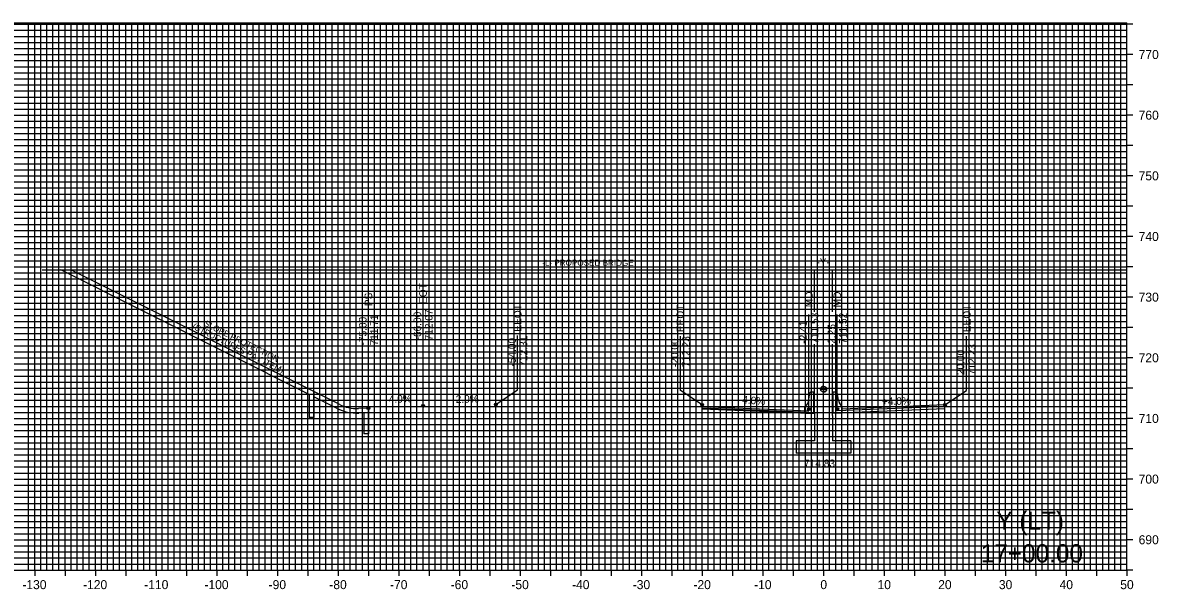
# Model space of a CAD drawing. Extents: x -255 to 55, y 682 to 775.
# Drawn here: x -132 to 55.2, y 681.8 to 775.3 of the extents above; entities that cross this region are included whole.
import ezdxf

# ---------------------------------------------------------------- set-up
doc = ezdxf.new("R2010")
doc.units = 0
for name, color, linetype in [('Default', 7, 'Continuous'), ('Draft_Corridor_Graphics_Conceptual', 7, 'Continuous'), ('Draft_Corridor_Point_Control', 7, 'Continuous'), ('E_NCDOT_Vertical_Profile_Ground_Line', 7, 'Continuous'), ('P_HYD_Contour_Major', 7, 'Continuous'), ('P_HYD_Contour_Minor', 7, 'Continuous'), ('P_HYD_TC_Ditch_DDE', 7, 'Continuous'), ('P_HYD_TC_Ditch_UCE', 7, 'Continuous'), ('P_HYD_TC_Surface_Grass', 7, 'Continuous'), ('P_HYD_TL_Slope_Stake_Fill', 7, 'Continuous'), ('P_HYD_Watershed_Grass_C_03', 7, 'Continuous'), ('P_HYD_Watershed_Impervious_C_09', 7, 'Continuous'), ('P_NCDOT_Terrain_Breakline', 7, 'Continuous'), ('P_NCDOT_Terrain_Flow_Arrows', 7, 'Continuous'), ('P_NCDOT_Terrain_Hole', 7, 'Continuous'), ('P_NCDOT_Terrain_Island', 7, 'Continuous'), ('P_NCDOT_Terrain_Points_High', 7, 'Continuous'), ('Scratch_Level_0', 7, 'Continuous')]:
    doc.layers.add(name, color=color, linetype=linetype)

msp = doc.modelspace()

# ---------------------------------------------------------------- linework, layer by layer
at = {"layer": 'Default'}
for p, q in [((-128.74, 734.49), (49.99, 734.49)), ((0, 714.83), (0, 734.41)), ((-20.03, 711.57), (-2.44, 710.86)), ((-20.02, 711.73), (-2.43, 711.03)), ((-20.01, 711.98), (-2.42, 711.28)), ((20, 711.99), (2.28, 711.28)), ((20, 711.57), (2.3, 710.86))]:
    msp.add_line(p, q, dxfattribs=at)
at = {"layer": 'Draft_Corridor_Point_Control'}
for p, q in [((0, 715.33), (0, 714.33)), ((-0.5, 714.83), (0.5, 714.83))]:
    msp.add_line(p, q, dxfattribs=at)
for points in [[(-0.5, 714.83), (0, 714.83), (0, 715.33)], [(0.5, 714.83), (0, 714.83), (0, 714.33)]]:
    msp.add_lwpolyline(points, dxfattribs=at)
msp.add_circle((0, 714.83), 0.5, dxfattribs=at)
for start, end in [(90, 180), (270, 0)]:
    msp.add_arc((0, 714.83), 0.5, start, end, dxfattribs=at)
at = {"layer": 'P_HYD_Contour_Major'}
for p, q in [((-131, 685), (-131, 775.25)), ((-129, 685), (-129, 775.25)), ((-128, 685), (-128, 775.25)), ((-127, 685), (-127, 775.25)), ((-126, 685), (-126, 775.25)), ((-124, 685), (-124, 775.25)), ((-123, 685), (-123, 775.25)), ((-122, 685), (-122, 775.25)), ((-121, 685), (-121, 775.25)), ((-119, 685), (-119, 775.25)), ((-118, 685), (-118, 775.25)), ((-117, 685), (-117, 775.25)), ((-116, 685), (-116, 775.25)), ((-114, 685), (-114, 775.25)), ((-113, 685), (-113, 775.25)), ((-112, 685), (-112, 775.25)), ((-111, 685), (-111, 775.25)), ((-109, 685), (-109, 775.25)), ((-108, 685), (-108, 775.25)), ((-107, 685), (-107, 775.25)), ((-106, 685), (-106, 775.25)), ((-104, 685), (-104, 775.25)), ((-103, 685), (-103, 775.25)), ((-102, 685), (-102, 775.25)), ((-101, 685), (-101, 775.25)), ((-99, 685), (-99, 775.25)), ((-98, 685), (-98, 775.25)), ((-97, 685), (-97, 775.25)), ((-96, 685), (-96, 775.25)), ((-94, 685), (-94, 775.25)), ((-93, 685), (-93, 775.25)), ((-92, 685), (-92, 775.25)), ((-91, 685), (-91, 775.25)), ((-89, 685), (-89, 775.25)), ((-88, 685), (-88, 775.25)), ((-87, 685), (-87, 775.25)), ((-86, 685), (-86, 775.25)), ((-84, 685), (-84, 775.25)), ((-83, 685), (-83, 775.25)), ((-82, 685), (-82, 775.25)), ((-81, 685), (-81, 775.25)), ((-79, 685), (-79, 775.25)), ((-78, 685), (-78, 775.25)), ((-77, 685), (-77, 775.25)), ((-76, 685), (-76, 775.25)), ((-74, 685), (-74, 775.25)), ((-73, 685), (-73, 775.25)), ((-72, 685), (-72, 775.25)), ((-71, 685), (-71, 775.25)), ((-69, 685), (-69, 775.25)), ((-68, 685), (-68, 775.25)), ((-67, 685), (-67, 775.25)), ((-66, 685), (-66, 775.25)), ((-64, 685), (-64, 775.25)), ((-63, 685), (-63, 775.25)), ((-62, 685), (-62, 775.25)), ((-61, 685), (-61, 775.25)), ((-59, 685), (-59, 775.25)), ((-58, 685), (-58, 775.25)), ((-57, 685), (-57, 775.25)), ((-56, 685), (-56, 775.25)), ((-54, 685), (-54, 775.25)), ((-53, 685), (-53, 775.25)), ((-52, 685), (-52, 775.25)), ((-51, 685), (-51, 775.25)), ((-49, 685), (-49, 775.25)), ((-48, 685), (-48, 775.25)), ((-47, 685), (-47, 775.25)), ((-46, 685), (-46, 775.25)), ((-44, 685), (-44, 775.25)), ((-43, 685), (-43, 775.25)), ((-42, 685), (-42, 775.25)), ((-41, 685), (-41, 775.25)), ((-39, 685), (-39, 775.25)), ((-38, 685), (-38, 775.25)), ((-37, 685), (-37, 775.25)), ((-36, 685), (-36, 775.25)), ((-34, 685), (-34, 775.25)), ((-33, 685), (-33, 775.25)), ((-32, 685), (-32, 775.25)), ((-31, 685), (-31, 775.25)), ((-29, 685), (-29, 775.25)), ((-28, 685), (-28, 775.25)), ((-27, 685), (-27, 775.25)), ((-26, 685), (-26, 775.25)), ((-24, 685), (-24, 775.25)), ((-23, 685), (-23, 775.25)), ((-22, 685), (-22, 775.25)), ((-21, 685), (-21, 775.25)), ((-19, 685), (-19, 775.25)), ((-18, 685), (-18, 775.25)), ((-17, 685), (-17, 775.25)), ((-16, 685), (-16, 775.25)), ((-14, 685), (-14, 775.25)), ((-13, 685), (-13, 775.25)), ((-12, 685), (-12, 775.25)), ((-11, 685), (-11, 775.25)), ((-9, 685), (-9, 775.25)), ((-8, 685), (-8, 775.25)), ((-7, 685), (-7, 775.25)), ((-6, 685), (-6, 775.25)), ((-4, 685), (-4, 775.25)), ((-3, 685), (-3, 775.25)), ((-2, 685), (-2, 775.25)), ((-1, 685), (-1, 775.25)), ((1, 685), (1, 775.25)), ((2, 685), (2, 775.25)), ((3, 685), (3, 775.25)), ((4, 685), (4, 775.25)), ((6, 685), (6, 775.25)), ((7, 685), (7, 775.25)), ((8, 685), (8, 775.25)), ((9, 685), (9, 775.25)), ((11, 685), (11, 775.25)), ((12, 685), (12, 775.25)), ((13, 685), (13, 775.25)), ((14, 685), (14, 775.25)), ((16, 685), (16, 775.25)), ((17, 685), (17, 775.25)), ((18, 685), (18, 775.25)), ((19, 685), (19, 775.25)), ((21, 685), (21, 775.25)), ((22, 685), (22, 775.25)), ((23, 685), (23, 775.25)), ((24, 685), (24, 775.25)), ((26, 685), (26, 775.25)), ((27, 685), (27, 775.25)), ((28, 685), (28, 775.25)), ((29, 685), (29, 775.25)), ((31, 685), (31, 775.25)), ((32, 685), (32, 775.25)), ((33, 685), (33, 775.25)), ((34, 685), (34, 775.25)), ((36, 685), (36, 775.25)), ((37, 685), (37, 775.25)), ((38, 685), (38, 775.25)), ((39, 685), (39, 775.25)), ((41, 685), (41, 775.25)), ((42, 685), (42, 775.25)), ((43, 685), (43, 775.25)), ((44, 685), (44, 775.25)), ((46, 685), (46, 775.25)), ((47, 685), (47, 775.25)), ((48, 685), (48, 775.25)), ((49, 685), (49, 775.25)), ((-250, 774), (50, 774)), ((-250, 773), (50, 773)), ((-250, 772), (50, 772)), ((-250, 771), (50, 771)), ((-250, 769), (50, 769)), ((-250, 768), (50, 768)), ((-250, 767), (50, 767)), ((-250, 766), (50, 766)), ((-250, 764), (50, 764)), ((-250, 763), (50, 763)), ((-250, 762), (50, 762)), ((-250, 761), (50, 761)), ((-250, 759), (50, 759)), ((-250, 758), (50, 758)), ((-250, 757), (50, 757)), ((-250, 756), (50, 756)), ((-250, 754), (50, 754)), ((-250, 753), (50, 753)), ((-250, 752), (50, 752)), ((-250, 751), (50, 751)), ((-250, 749), (50, 749)), ((-250, 748), (50, 748)), ((-250, 747), (50, 747)), ((-250, 746), (50, 746)), ((-250, 744), (50, 744)), ((-250, 743), (50, 743)), ((-250, 742), (50, 742)), ((-250, 741), (50, 741)), ((-250, 739), (50, 739)), ((-250, 738), (50, 738)), ((-250, 737), (50, 737)), ((-250, 736), (50, 736)), ((-250, 734), (50, 734)), ((-250, 733), (50, 733)), ((-250, 732), (50, 732)), ((-250, 731), (50, 731)), ((-250, 729), (50, 729)), ((-250, 728), (50, 728)), ((-250, 727), (50, 727)), ((-250, 726), (50, 726)), ((-250, 724), (50, 724)), ((-250, 723), (50, 723)), ((-250, 722), (50, 722)), ((-250, 721), (50, 721)), ((-250, 719), (50, 719)), ((-250, 718), (50, 718)), ((-250, 717), (50, 717)), ((-250, 716), (50, 716)), ((-250, 714), (50, 714)), ((-250, 713), (50, 713)), ((-250, 712), (50, 712)), ((-250, 711), (50, 711)), ((-250, 709), (50, 709)), ((-250, 708), (50, 708)), ((-250, 707), (50, 707)), ((-250, 706), (50, 706)), ((-250, 704), (50, 704)), ((-250, 703), (50, 703)), ((-250, 702), (50, 702)), ((-250, 701), (50, 701)), ((-250, 699), (50, 699)), ((-250, 698), (50, 698)), ((-250, 697), (50, 697)), ((-250, 696), (50, 696)), ((-250, 694), (50, 694)), ((-250, 693), (50, 693)), ((-250, 692), (50, 692)), ((-250, 691), (50, 691)), ((-250, 689), (50, 689)), ((-250, 688), (50, 688)), ((-250, 687), (50, 687)), ((-250, 686), (50, 686))]:
    msp.add_line(p, q, dxfattribs=at)
at = {"layer": 'P_HYD_Contour_Minor'}
for p, q in [((-250, 775), (50, 775)), ((-130, 685), (-130, 775.25)), ((-125, 685), (-125, 775.25)), ((-120, 685), (-120, 775.25)), ((-115, 685), (-115, 775.25)), ((-110, 685), (-110, 775.25)), ((-105, 685), (-105, 775.25)), ((-100, 685), (-100, 775.25)), ((-95, 685), (-95, 775.25)), ((-90, 685), (-90, 775.25)), ((-85, 685), (-85, 775.25)), ((-80, 685), (-80, 775.25)), ((-75, 685), (-75, 775.25)), ((-70, 685), (-70, 775.25)), ((-65, 685), (-65, 775.25)), ((-60, 685), (-60, 775.25)), ((-55, 685), (-55, 775.25)), ((-50, 685), (-50, 775.25)), ((-45, 685), (-45, 775.25)), ((-40, 685), (-40, 775.25)), ((-35, 685), (-35, 775.25)), ((-30, 685), (-30, 775.25)), ((-25, 685), (-25, 775.25)), ((-20, 685), (-20, 775.25)), ((-15, 685), (-15, 775.25)), ((-10, 685), (-10, 775.25)), ((-5, 685), (-5, 775.25)), ((0, 685), (0, 775.25)), ((5, 685), (5, 775.25)), ((10, 685), (10, 775.25)), ((15, 685), (15, 775.25)), ((20, 685), (20, 775.25)), ((25, 685), (25, 775.25)), ((30, 685), (30, 775.25)), ((35, 685), (35, 775.25)), ((40, 685), (40, 775.25)), ((45, 685), (45, 775.25)), ((50.96, 775), (50, 775)), ((-250, 770), (50, 770)), ((50.96, 770), (50, 770)), ((-250, 765), (50, 765)), ((50.96, 765), (50, 765)), ((-250, 760), (50, 760)), ((50.96, 760), (50, 760)), ((-250, 755), (50, 755)), ((50.96, 755), (50, 755)), ((-250, 750), (50, 750)), ((50.96, 750), (50, 750)), ((-250, 745), (50, 745)), ((50.96, 745), (50, 745)), ((-250, 740), (50, 740)), ((50.96, 740), (50, 740)), ((-250, 735), (50, 735)), ((50.96, 735), (50, 735)), ((-250, 730), (50, 730)), ((50.96, 730), (50, 730)), ((-250, 725), (50, 725)), ((50.96, 725), (50, 725)), ((-250, 720), (50, 720)), ((50.96, 720), (50, 720)), ((-250, 715), (50, 715)), ((50.96, 715), (50, 715)), ((-250, 710), (50, 710)), ((50.96, 710), (50, 710)), ((-250, 705), (50, 705)), ((50.96, 705), (50, 705)), ((-250, 700), (50, 700)), ((50.96, 700), (50, 700)), ((-250, 695), (50, 695)), ((50.96, 695), (50, 695)), ((-250, 690), (50, 690)), ((50.96, 690), (50, 690)), ((-130, 685), (-130, 684.04)), ((-125, 685), (-125, 684.04)), ((-120, 685), (-120, 684.04)), ((-115, 685), (-115, 684.04)), ((-110, 685), (-110, 684.04)), ((-105, 685), (-105, 684.04)), ((-100, 685), (-100, 684.04)), ((-95, 685), (-95, 684.04)), ((-90, 685), (-90, 684.04)), ((-85, 685), (-85, 684.04)), ((-80, 685), (-80, 684.04)), ((-75, 685), (-75, 684.04)), ((-70, 685), (-70, 684.04)), ((-65, 685), (-65, 684.04)), ((-60, 685), (-60, 684.04)), ((-55, 685), (-55, 684.04)), ((-50, 685), (-50, 684.04)), ((-45, 685), (-45, 684.04)), ((-40, 685), (-40, 684.04)), ((-35, 685), (-35, 684.04)), ((-30, 685), (-30, 684.04)), ((-25, 685), (-25, 684.04)), ((-20, 685), (-20, 684.04)), ((-15, 685), (-15, 684.04)), ((-10, 685), (-10, 684.04)), ((-5, 685), (-5, 684.04)), ((0, 685), (0, 684.04)), ((5, 685), (5, 684.04)), ((10, 685), (10, 684.04)), ((15, 685), (15, 684.04)), ((20, 685), (20, 684.04)), ((25, 685), (25, 684.04)), ((30, 685), (30, 684.04)), ((35, 685), (35, 684.04)), ((40, 685), (40, 684.04)), ((45, 685), (45, 684.04)), ((50, 685), (50, 684.04)), ((50.96, 685), (50, 685))]:
    msp.add_line(p, q, dxfattribs=at)
at = {"layer": 'P_HYD_TC_Ditch_DDE'}
for p, q in [((-130, 685), (-130, 775.25)), ((-120, 685), (-120, 775.25)), ((-110, 685), (-110, 775.25)), ((-100, 685), (-100, 775.25)), ((-90, 685), (-90, 775.25)), ((-80, 685), (-80, 775.25)), ((-70, 685), (-70, 775.25)), ((-60, 685), (-60, 775.25)), ((-50, 685), (-50, 775.25)), ((-50, 685), (-50, 775.25)), ((-40, 685), (-40, 775.25)), ((-30, 685), (-30, 775.25)), ((-20, 685), (-20, 775.25)), ((-10, 685), (-10, 775.25)), ((0, 685), (0, 775.25)), ((10, 685), (10, 775.25)), ((20, 685), (20, 775.25)), ((30, 685), (30, 775.25)), ((40, 685), (40, 775.25)), ((-250, 770), (50, 770)), ((-250, 760), (50, 760)), ((-250, 750), (50, 750)), ((-250, 740), (50, 740)), ((-250, 730), (50, 730)), ((-250, 720), (50, 720)), ((-250, 710), (50, 710)), ((-250, 700), (50, 700)), ((-250, 690), (50, 690))]:
    msp.add_line(p, q, dxfattribs=at)
at = {"layer": 'P_HYD_TC_Ditch_UCE'}
for centre in [(0, 714.83), (0, 714.82), (-75, 711.71), (-75, 711.71), (-66, 712.07), (-66, 712.07), (-54, 712.31), (-54, 712.31), (-20, 712.23), (-2.41, 711.53), (2.25, 711.52), (20, 712.23)]:
    msp.add_circle(centre, 0.05, dxfattribs=at)
at = {"layer": 'P_HYD_TL_Slope_Stake_Fill'}
for p, q in [((-250, 775.25), (50, 775.25)), ((50, 685), (50, 775.25)), ((-250, 685), (50, 685))]:
    msp.add_line(p, q, dxfattribs=at)
at = {"layer": 'P_HYD_Watershed_Impervious_C_09'}
for p, q in [((-50.44, 714.71), (-50.44, 723.66)), ((-23.56, 714.63), (-23.56, 723.58)), ((23.56, 714.63), (23.56, 723.58)), ((-54, 712.31), (-50.44, 714.71)), ((-20, 712.23), (-23.56, 714.63)), ((20, 712.23), (23.56, 714.63))]:
    msp.add_line(p, q, dxfattribs=at)
at = {"layer": 'P_NCDOT_Terrain_Hole'}
msp.add_line((20, 712.23), (3.08, 711.56), dxfattribs=at)
at = {"layer": 'P_NCDOT_Terrain_Island'}
for points in [[(-2.46, 712.83), (-2.25, 714.24)], [(-1.58, 710.81), (-1.58, 714.31), (-2.17, 714.31)], [(1.58, 710.91), (1.58, 714.41), (2.17, 714.41)], [(2.46, 712.94), (2.25, 714.34)], [(-1.58, 710.81), (-3.08, 710.81), (-3.08, 711.56), (-3.08, 711.81), (-2.6, 712.48)], [(1.58, 710.91), (3.08, 710.91), (3.08, 711.66), (3.08, 711.91), (2.6, 712.58)]]:
    msp.add_lwpolyline(points, dxfattribs=at)
for centre, radius, start, end in [((-2.17, 714.22), 0.0833, 90, 171.4692), ((2.17, 714.33), 0.0833, 8.5308, 90), ((-3.29, 712.96), 0.833, 325.008, 351.4692), ((3.29, 713.06), 0.833, 188.5308, 214.992)]:
    msp.add_arc(centre, radius, start, end, dxfattribs=at)
at = {"layer": 'P_NCDOT_Terrain_Points_High'}
for p, q in [((-84.75, 713.96), (-125.71, 734.49)), ((-79.83, 712.34), (-124.04, 734.49)), ((-1.5, 727.6), (-1.5, 734.38)), ((1.5, 727.6), (1.5, 734.38)), ((-1.5, 710.98), (-1.5, 722.26)), ((1.5, 710.5), (1.5, 722.26)), ((-84.75, 713.96), (-84.75, 710.18)), ((-84, 714.43), (-84, 710.18)), ((-80.17, 711.67), (-84, 713.59)), ((-75, 711.71), (-76.63, 711.65)), ((-75, 711.71), (-75, 707.45)), ((-84, 710.18), (-84.75, 710.18)), ((-75.75, 710.93), (-76.6, 710.9)), ((-75.75, 710.93), (-75.75, 707.45)), ((-1.5, 710.98), (-1.5, 706.29)), ((1.5, 710.5), (1.5, 706.29)), ((-75, 707.45), (-75.75, 707.45)), ((-1.5, 706.29), (-4.5, 706.29)), ((-4.5, 706.29), (-4.5, 704.29)), ((4.5, 706.29), (1.5, 706.29)), ((4.5, 706.29), (4.5, 704.29)), ((4.5, 704.29), (-4.5, 704.29))]:
    msp.add_line(p, q, dxfattribs=at)
for radius in [7.32, 6.57]:
    msp.add_arc((-76.89, 718.21), radius, 243.3788, 272.2621, dxfattribs=at)
at = {"layer": 'Scratch_Level_0'}
for p, q in [((-75, 711.71), (-75, 727.31)), ((-66, 712.07), (-66, 727.67)), ((-2.41, 711.53), (-2.41, 727.13)), ((2.25, 711.52), (2.25, 727.12))]:
    msp.add_line(p, q, dxfattribs=at)
for centre in [(-75, 711.71), (-66, 712.07), (-54, 712.31), (-20, 712.23), (-2.41, 711.53), (2.25, 711.52), (20, 712.23)]:
    msp.add_circle(centre, 0.24, dxfattribs=at)

# ---------------------------------------------------------------- texts
at = {"layer": 'Draft_Corridor_Graphics_Conceptual'}
for s, rotation, p in [('-4.0%', 1.512, (-72.2, 712.55)), ('-2.0%', 1.1835, (-61.17, 712.54)), ('-4.0%', 355.2171, (-14, 712.55)), ('+4.0%', 1.512, (9.63, 712.17))]:
    msp.add_text(s, height=1.248, rotation=rotation, dxfattribs=at).set_placement(p)
at = {"layer": 'E_NCDOT_Vertical_Profile_Ground_Line'}
for s, height, p in [('770', 1.488, (51.92, 769.26)), ('760', 1.488, (51.92, 759.26)), ('750', 1.488, (51.92, 749.26)), ('740', 1.488, (51.92, 739.26)), ('730', 1.488, (51.92, 729.26)), ('720', 1.488, (51.92, 719.26)), ('710', 1.488, (51.92, 709.26)), ('700', 1.488, (51.92, 699.26)), ('690', 1.488, (51.92, 689.26)), ('-130', 1.488, (-132.03, 681.86)), ('-120', 1.488, (-122.03, 681.86)), ('-110', 1.488, (-111.95, 681.86)), ('-100', 1.488, (-102.03, 681.86)), ('-90', 1.488, (-91.45, 681.86)), ('-80', 1.488, (-81.45, 681.86)), ('-70', 1.488, (-71.45, 681.86)), ('-60', 1.488, (-61.45, 681.86)), ('-50', 1.488, (-51.45, 681.86)), ('-40', 1.488, (-41.45, 681.86)), ('-30', 1.488, (-31.45, 681.86)), ('-20', 1.488, (-21.45, 681.86)), ('-10', 1.488, (-11.45, 681.86)), ('0', 1.49, (-0.53, 681.86)), ('10', 1.488, (8.89, 681.86)), ('20', 1.488, (18.89, 681.86)), ('30', 1.488, (28.89, 681.86)), ('40', 1.488, (38.89, 681.86)), ('50', 1.488, (48.89, 681.86))]:
    msp.add_text(s, height=height, dxfattribs=at).set_placement(p)
at = {"layer": 'P_HYD_TC_Surface_Grass'}
for s, p in [('Y (LT)', (28.47, 691.66)), ('17+00.00', (25.9, 686.26))]:
    msp.add_text(s, height=3, dxfattribs=at).set_placement(p)
at = {"layer": 'P_HYD_Watershed_Grass_C_03'}
for s, p in [('EOT', (-65.38, 728.87)), ('PS', (-74.38, 728.51)), ('MD', (-1.79, 728.33)), ('MD', (2.88, 728.32)), ('EEOT', (-49.78, 724.31)), ('EEOT', (-22.98, 724.23)), ('EEOT', (24.22, 724.23)), ('-75.00', (-75.31, 722.03)), ('711.71', (-73.44, 722.03)), ('-66.00', (-66.31, 722.87)), ('712.07', (-64.44, 722.87)), ('711.53', (-0.85, 722.33)), ('711.52', (3.81, 722.32)), ('-2.41', (-2.73, 722.33)), ('2.25', (1.94, 722.32)), ('-54.00', (-50.71, 718.55)), ('712.31', (-48.84, 718.55)), ('-20.00', (-23.91, 718.47)), ('712.23', (-22.04, 718.47)), ('20.00', (23.21, 717.15)), ('712.23', (25.08, 717.15))]:
    msp.add_text(s, height=1.248, rotation=90, dxfattribs=at).set_placement(p)
at = {"layer": 'P_NCDOT_Terrain_Breakline'}
for s, rotation, p in [('-L- PROPOSED BRIDGE', 359.7912, (-46.37, 735.21)), ('SLOPE PROTECTION', 333.3788, (-102.2, 725.35)), ('(STRUCTURES PAY ITEM)', 333.3788, (-104.13, 724.86))]:
    msp.add_text(s, height=1, rotation=rotation, dxfattribs=at).set_placement(p)
at = {"layer": 'P_NCDOT_Terrain_Flow_Arrows'}
for s, p in [('-Y-', (-1.2, 735.18)), ('714.83', (-3.22, 701.98))]:
    msp.add_text(s, height=1.248, dxfattribs=at).set_placement(p)

doc.saveas('drawing.dxf')
